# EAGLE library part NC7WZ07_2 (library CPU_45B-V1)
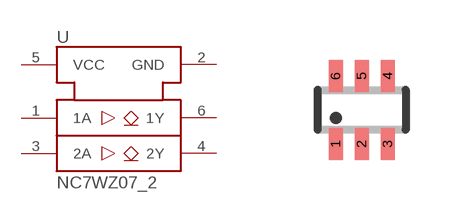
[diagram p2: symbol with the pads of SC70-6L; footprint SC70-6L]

Designator prefix U

## NC7WZ07_2P6X  [SC70-6L]
1  1A  in
2  GND  pwr
3  2A  in
4  2Y  out
5  VCC  pwr
6  1Y  out

## Footprint SC70-6L (pad centres in mm)
SC-70 Package
smd 0.35 x 0.8: 1 -0.65,-0.85; 2 0,-0.85; 3 0.65,-0.85; 4 0.65,0.85; 5 0,0.85; 6 -0.65,0.85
